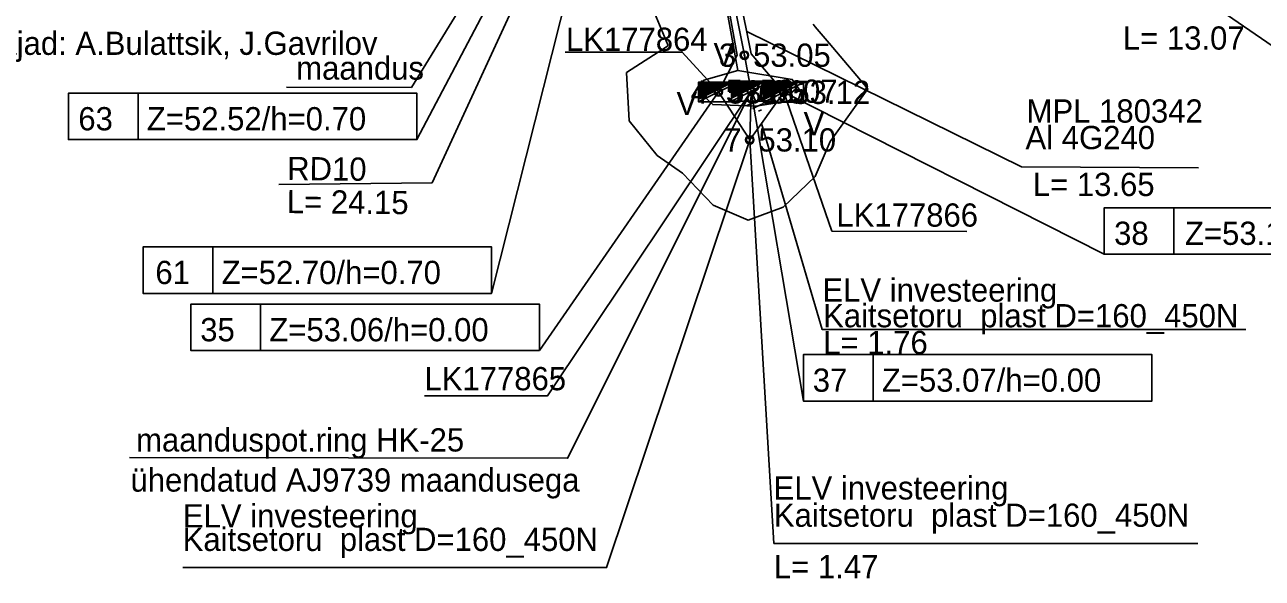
# Model space of a CAD drawing. Extents: x 592082 to 595437, y 6463338 to 6467739.
# Drawn here: x 592385.16 to 592422.46, y 6466209.4 to 6466226.07 of the extents above; entities that cross this region are included whole.
import ezdxf

# ---------------------------------------------------------------- set-up
doc = ezdxf.new("R2010")
doc.units = 0
for name, color, linetype in [('ABIJOONIS', 7, 'Continuous'), ('ELRAJATISMP', 7, 'Continuous'), ('KOORDPUNKT', 7, 'Continuous'), ('MOOTKORG-EH2000', 7, 'Continuous'), ('MOOTMPUNKT', 7, 'Continuous'), ('MOOTNR', 7, 'Continuous'), ('MOOTPIIR', 7, 'Continuous'), ('MPKAABEL', 7, 'Continuous'), ('RAJATIS', 7, 'Continuous'), ('TEE', 7, 'Continuous')]:
    doc.layers.add(name, color=color, linetype=linetype)

msp = doc.modelspace()

# ---------------------------------------------------------------- linework, layer by layer
at = {"layer": 'ABIJOONIS'}
for points in [[(592402.61, 6466231.398), (592399.232, 6466217.982), (592388.732, 6466217.982), (592388.732, 6466219.382), (592399.232, 6466219.382), (592399.232, 6466217.982)], [(592400.927, 6466230.114), (592396.98, 6466222.613), (592386.48, 6466222.613), (592386.48, 6466224.013), (592396.98, 6466224.013), (592396.98, 6466222.613)], [(592388.58, 6466222.613), (592388.58, 6466224.013)], [(592406.069, 6466224.05), (592400.672, 6466216.257), (592390.172, 6466216.257), (592390.172, 6466217.657), (592400.672, 6466217.657), (592400.672, 6466216.257)], [(592407.056, 6466224.073), (592408.631, 6466214.737), (592419.131, 6466214.737), (592419.131, 6466216.137), (592408.631, 6466216.137), (592408.631, 6466214.737)], [(592408.036, 6466224.039), (592417.694, 6466219.162), (592428.194, 6466219.162), (592428.194, 6466220.562), (592417.694, 6466220.562), (592417.694, 6466219.162)], [(592419.794, 6466219.162), (592419.794, 6466220.562)], [(592390.832, 6466217.982), (592390.832, 6466219.382)], [(592392.272, 6466216.257), (592392.272, 6466217.657)], [(592410.731, 6466214.737), (592410.731, 6466216.137)]]:
    msp.add_lwpolyline(points, dxfattribs=at)
at = {"layer": 'ELRAJATISMP'}
for p, q in [((592405.472, 6466224.344), (592405.476, 6466224.348)), ((592405.472, 6466224.33), (592405.49, 6466224.348)), ((592405.472, 6466224.316), (592405.504, 6466224.348)), ((592405.472, 6466224.302), (592405.518, 6466224.348)), ((592405.472, 6466224.288), (592405.532, 6466224.348)), ((592405.472, 6466224.274), (592405.547, 6466224.348)), ((592405.472, 6466224.259), (592405.561, 6466224.348)), ((592405.472, 6466224.245), (592405.575, 6466224.348)), ((592405.472, 6466224.231), (592405.589, 6466224.348)), ((592405.472, 6466224.217), (592405.603, 6466224.348)), ((592405.472, 6466224.203), (592405.617, 6466224.348)), ((592405.472, 6466224.189), (592405.631, 6466224.348)), ((592405.472, 6466224.175), (592405.646, 6466224.348)), ((592405.472, 6466224.16), (592405.66, 6466224.348)), ((592405.472, 6466224.146), (592405.674, 6466224.348)), ((592405.472, 6466224.132), (592405.688, 6466224.348)), ((592405.472, 6466224.118), (592405.702, 6466224.348)), ((592405.472, 6466224.104), (592405.716, 6466224.348)), ((592405.472, 6466224.09), (592405.73, 6466224.348)), ((592405.472, 6466224.076), (592405.745, 6466224.348)), ((592405.472, 6466224.061), (592405.759, 6466224.348)), ((592405.472, 6466224.047), (592405.773, 6466224.348)), ((592405.472, 6466224.033), (592405.787, 6466224.348)), ((592405.472, 6466224.019), (592405.801, 6466224.348)), ((592405.472, 6466224.005), (592405.815, 6466224.348)), ((592405.472, 6466223.991), (592405.829, 6466224.348)), ((592405.472, 6466223.977), (592405.844, 6466224.348)), ((592405.472, 6466223.962), (592405.858, 6466224.348)), ((592405.472, 6466223.948), (592405.872, 6466224.348)), ((592405.472, 6466223.934), (592405.886, 6466224.348)), ((592405.472, 6466223.92), (592405.9, 6466224.348)), ((592405.472, 6466223.906), (592405.914, 6466224.348)), ((592405.472, 6466223.892), (592405.928, 6466224.348)), ((592405.472, 6466223.878), (592405.943, 6466224.348)), ((592405.472, 6466223.863), (592405.957, 6466224.348)), ((592405.472, 6466223.849), (592405.971, 6466224.348)), ((592405.472, 6466223.836), (592405.985, 6466224.348)), ((592405.5, 6466223.85), (592405.999, 6466224.348)), ((592405.529, 6466223.864), (592406.013, 6466224.348)), ((592405.557, 6466223.878), (592406.027, 6466224.348)), ((592405.585, 6466223.892), (592406.042, 6466224.348)), ((592405.614, 6466223.906), (592406.056, 6466224.348)), ((592405.642, 6466223.92), (592406.07, 6466224.348)), ((592405.67, 6466223.935), (592406.084, 6466224.348)), ((592405.698, 6466223.949), (592406.098, 6466224.348)), ((592405.727, 6466223.963), (592406.112, 6466224.348)), ((592405.755, 6466223.977), (592406.126, 6466224.348)), ((592405.783, 6466223.991), (592406.141, 6466224.348)), ((592405.811, 6466224.005), (592406.155, 6466224.348)), ((592405.84, 6466224.019), (592406.169, 6466224.348)), ((592405.868, 6466224.033), (592406.183, 6466224.348)), ((592405.896, 6466224.047), (592406.197, 6466224.348)), ((592405.924, 6466224.062), (592406.211, 6466224.348)), ((592405.953, 6466224.076), (592406.225, 6466224.348)), ((592405.981, 6466224.09), (592406.24, 6466224.348)), ((592406.009, 6466224.104), (592406.254, 6466224.348)), ((592406.038, 6466224.118), (592406.268, 6466224.348)), ((592406.066, 6466224.132), (592406.282, 6466224.348)), ((592406.094, 6466224.146), (592406.296, 6466224.348)), ((592406.122, 6466224.16), (592406.31, 6466224.348)), ((592406.151, 6466224.175), (592406.324, 6466224.348)), ((592406.179, 6466224.189), (592406.339, 6466224.348)), ((592406.207, 6466224.203), (592406.353, 6466224.348)), ((592406.235, 6466224.217), (592406.367, 6466224.348)), ((592406.264, 6466224.231), (592406.381, 6466224.348)), ((592406.292, 6466224.245), (592406.395, 6466224.348)), ((592406.32, 6466224.259), (592406.409, 6466224.348)), ((592406.348, 6466224.273), (592406.423, 6466224.348)), ((592406.377, 6466224.288), (592406.438, 6466224.348)), ((592406.405, 6466224.302), (592406.452, 6466224.348)), ((592406.433, 6466224.316), (592406.466, 6466224.348)), ((592406.459, 6466224.367), (592406.463, 6466224.371)), ((592406.459, 6466224.353), (592406.477, 6466224.371)), ((592406.459, 6466224.339), (592406.491, 6466224.371)), ((592406.459, 6466224.325), (592406.505, 6466224.371)), ((592406.459, 6466224.311), (592406.519, 6466224.371)), ((592406.459, 6466224.297), (592406.534, 6466224.371)), ((592406.459, 6466224.282), (592406.548, 6466224.371)), ((592406.459, 6466224.268), (592406.562, 6466224.371)), ((592406.459, 6466224.254), (592406.576, 6466224.371)), ((592406.459, 6466224.24), (592406.59, 6466224.371)), ((592406.459, 6466224.226), (592406.604, 6466224.371)), ((592406.459, 6466224.212), (592406.618, 6466224.371)), ((592406.459, 6466224.198), (592406.633, 6466224.371)), ((592406.459, 6466224.183), (592406.647, 6466224.371)), ((592406.459, 6466224.169), (592406.661, 6466224.371)), ((592406.459, 6466224.155), (592406.675, 6466224.371)), ((592406.459, 6466224.141), (592406.689, 6466224.371)), ((592406.459, 6466224.127), (592406.703, 6466224.371)), ((592406.459, 6466224.113), (592406.717, 6466224.371)), ((592406.459, 6466224.099), (592406.732, 6466224.371)), ((592406.459, 6466224.084), (592406.746, 6466224.371)), ((592406.459, 6466224.07), (592406.76, 6466224.371)), ((592406.459, 6466224.056), (592406.774, 6466224.371)), ((592406.459, 6466224.042), (592406.788, 6466224.371)), ((592406.459, 6466224.028), (592406.802, 6466224.371)), ((592406.459, 6466224.014), (592406.816, 6466224.371)), ((592406.459, 6466224), (592406.831, 6466224.371)), ((592406.459, 6466223.985), (592406.845, 6466224.371)), ((592406.459, 6466223.971), (592406.859, 6466224.371)), ((592406.459, 6466223.957), (592406.873, 6466224.371)), ((592406.459, 6466223.943), (592406.887, 6466224.371)), ((592406.459, 6466223.929), (592406.901, 6466224.371)), ((592406.459, 6466223.915), (592406.915, 6466224.371)), ((592406.459, 6466223.901), (592406.93, 6466224.371)), ((592406.459, 6466223.886), (592406.944, 6466224.371)), ((592406.459, 6466223.872), (592406.958, 6466224.371)), ((592406.459, 6466223.859), (592406.972, 6466224.371)), ((592406.462, 6466224.33), (592406.48, 6466224.348)), ((592406.487, 6466223.873), (592406.986, 6466224.371)), ((592406.49, 6466224.344), (592406.494, 6466224.348)), ((592406.498, 6466224.348), (592406.666, 6466224.348)), ((592406.516, 6466223.887), (592407, 6466224.371)), ((592406.544, 6466223.901), (592407.014, 6466224.371)), ((592406.572, 6466223.915), (592407.029, 6466224.371)), ((592406.601, 6466223.929), (592407.043, 6466224.371)), ((592406.629, 6466223.943), (592407.057, 6466224.371)), ((592406.657, 6466223.958), (592407.071, 6466224.371)), ((592406.685, 6466223.972), (592407.085, 6466224.371)), ((592406.714, 6466223.986), (592407.099, 6466224.371)), ((592406.742, 6466224), (592407.113, 6466224.371)), ((592406.77, 6466224.014), (592407.128, 6466224.371)), ((592406.798, 6466224.028), (592407.142, 6466224.371)), ((592406.827, 6466224.042), (592407.156, 6466224.371)), ((592406.855, 6466224.056), (592407.17, 6466224.371)), ((592406.883, 6466224.07), (592407.184, 6466224.371)), ((592406.911, 6466224.085), (592407.198, 6466224.371)), ((592406.94, 6466224.099), (592407.212, 6466224.371)), ((592406.968, 6466224.113), (592407.227, 6466224.371)), ((592406.996, 6466224.127), (592407.241, 6466224.371)), ((592407.025, 6466224.141), (592407.255, 6466224.371)), ((592407.053, 6466224.155), (592407.269, 6466224.371)), ((592407.081, 6466224.169), (592407.283, 6466224.371)), ((592407.109, 6466224.183), (592407.297, 6466224.371)), ((592407.138, 6466224.198), (592407.311, 6466224.371)), ((592407.166, 6466224.212), (592407.326, 6466224.371)), ((592407.194, 6466224.226), (592407.34, 6466224.371)), ((592407.222, 6466224.24), (592407.354, 6466224.371)), ((592407.251, 6466224.254), (592407.368, 6466224.371)), ((592407.279, 6466224.268), (592407.382, 6466224.371)), ((592407.307, 6466224.282), (592407.396, 6466224.371)), ((592407.335, 6466224.296), (592407.41, 6466224.371)), ((592407.364, 6466224.311), (592407.425, 6466224.371)), ((592407.392, 6466224.325), (592407.439, 6466224.371)), ((592407.42, 6466224.339), (592407.453, 6466224.371)), ((592407.439, 6466224.333), (592407.443, 6466224.337)), ((592407.439, 6466224.319), (592407.457, 6466224.337)), ((592407.439, 6466224.305), (592407.471, 6466224.337)), ((592407.439, 6466224.291), (592407.485, 6466224.337)), ((592407.439, 6466224.277), (592407.499, 6466224.337)), ((592407.439, 6466224.263), (592407.514, 6466224.337)), ((592407.439, 6466224.248), (592407.528, 6466224.337)), ((592407.439, 6466224.234), (592407.542, 6466224.337)), ((592407.439, 6466224.22), (592407.556, 6466224.337)), ((592407.439, 6466224.206), (592407.57, 6466224.337)), ((592407.439, 6466224.192), (592407.584, 6466224.337)), ((592407.439, 6466224.178), (592407.598, 6466224.337)), ((592407.439, 6466224.164), (592407.613, 6466224.337)), ((592407.439, 6466224.149), (592407.627, 6466224.337)), ((592407.439, 6466224.135), (592407.641, 6466224.337)), ((592407.439, 6466224.121), (592407.655, 6466224.337)), ((592407.439, 6466224.107), (592407.669, 6466224.337)), ((592407.439, 6466224.093), (592407.683, 6466224.337)), ((592407.439, 6466224.079), (592407.697, 6466224.337)), ((592407.439, 6466224.065), (592407.712, 6466224.337)), ((592407.439, 6466224.05), (592407.726, 6466224.337)), ((592407.439, 6466224.036), (592407.74, 6466224.337)), ((592407.439, 6466224.022), (592407.754, 6466224.337)), ((592407.439, 6466224.008), (592407.768, 6466224.337)), ((592407.439, 6466223.994), (592407.782, 6466224.337)), ((592407.439, 6466223.98), (592407.796, 6466224.337)), ((592407.439, 6466223.966), (592407.811, 6466224.337)), ((592407.439, 6466223.951), (592407.825, 6466224.337)), ((592407.439, 6466223.937), (592407.839, 6466224.337)), ((592407.439, 6466223.923), (592407.853, 6466224.337)), ((592407.439, 6466223.909), (592407.867, 6466224.337)), ((592407.439, 6466223.895), (592407.881, 6466224.337)), ((592407.439, 6466223.881), (592407.895, 6466224.337)), ((592407.439, 6466223.867), (592407.91, 6466224.337)), ((592407.439, 6466223.852), (592407.924, 6466224.337)), ((592407.439, 6466223.838), (592407.938, 6466224.337)), ((592407.439, 6466223.825), (592407.952, 6466224.337)), ((592407.449, 6466224.353), (592407.467, 6466224.371)), ((592407.467, 6466223.839), (592407.966, 6466224.337)), ((592407.477, 6466224.367), (592407.481, 6466224.371)), ((592407.485, 6466224.371), (592407.653, 6466224.371)), ((592407.496, 6466223.853), (592407.98, 6466224.337)), ((592407.524, 6466223.867), (592407.994, 6466224.337)), ((592407.552, 6466223.881), (592408.009, 6466224.337)), ((592407.581, 6466223.895), (592408.023, 6466224.337)), ((592407.609, 6466223.909), (592408.037, 6466224.337)), ((592407.637, 6466223.924), (592408.051, 6466224.337)), ((592407.665, 6466223.938), (592408.065, 6466224.337)), ((592407.694, 6466223.952), (592408.079, 6466224.337)), ((592407.722, 6466223.966), (592408.093, 6466224.337)), ((592407.75, 6466223.98), (592408.108, 6466224.337)), ((592407.778, 6466223.994), (592408.122, 6466224.337)), ((592407.807, 6466224.008), (592408.136, 6466224.337)), ((592407.835, 6466224.022), (592408.15, 6466224.337)), ((592407.863, 6466224.036), (592408.164, 6466224.337)), ((592407.891, 6466224.051), (592408.178, 6466224.337)), ((592407.92, 6466224.065), (592408.192, 6466224.337)), ((592407.948, 6466224.079), (592408.207, 6466224.337)), ((592407.976, 6466224.093), (592408.221, 6466224.337)), ((592408.005, 6466224.107), (592408.235, 6466224.337)), ((592408.033, 6466224.121), (592408.249, 6466224.337)), ((592408.061, 6466224.135), (592408.263, 6466224.337)), ((592408.089, 6466224.149), (592408.277, 6466224.337)), ((592408.118, 6466224.164), (592408.291, 6466224.337)), ((592408.146, 6466224.178), (592408.306, 6466224.337)), ((592408.174, 6466224.192), (592408.32, 6466224.337)), ((592408.202, 6466224.206), (592408.334, 6466224.337)), ((592408.231, 6466224.22), (592408.348, 6466224.337)), ((592408.259, 6466224.234), (592408.362, 6466224.337)), ((592408.287, 6466224.248), (592408.376, 6466224.337)), ((592408.315, 6466224.262), (592408.39, 6466224.337)), ((592408.344, 6466224.277), (592408.405, 6466224.337)), ((592408.372, 6466224.291), (592408.419, 6466224.337)), ((592408.4, 6466224.305), (592408.433, 6466224.337)), ((592408.429, 6466224.319), (592408.447, 6466224.337)), ((592408.457, 6466224.333), (592408.461, 6466224.337)), ((592408.465, 6466224.337), (592408.633, 6466224.337)), ((592405.472, 6466223.835), (592405.472, 6466223.752)), ((592406.459, 6466223.858), (592406.459, 6466223.775)), ((592407.439, 6466223.824), (592407.439, 6466223.741))]:
    msp.add_line(p, q, dxfattribs=at)
for points in [[(592406.069, 6466224.05), (592404.974, 6466225.253), (592401.445, 6466225.253)], [(592407.056, 6466224.073), (592400.918, 6466214.898), (592397.209, 6466214.898)], [(592408.036, 6466224.039), (592409.49, 6466219.86), (592413.556, 6466219.843)]]:
    msp.add_lwpolyline(points, dxfattribs=at)
for points in [[(592406.666, 6466224.348), (592405.472, 6466223.752), (592406.666, 6466223.752)], [(592405.472, 6466223.835), (592405.472, 6466224.348), (592406.498, 6466224.348)], [(592407.653, 6466224.371), (592406.459, 6466223.775), (592407.653, 6466223.775)], [(592406.459, 6466223.858), (592406.459, 6466224.371), (592407.485, 6466224.371)], [(592408.633, 6466224.337), (592407.439, 6466223.741), (592408.633, 6466223.741)], [(592407.439, 6466223.824), (592407.439, 6466224.337), (592408.465, 6466224.337)]]:
    msp.add_lwpolyline(points, close=True, dxfattribs=at)
at = {"layer": 'KOORDPUNKT'}
for centre, radius in [((592406.852, 6466225.157), 0.125), ((592406.852, 6466225.157), 0.0125), ((592406.852, 6466225.157), 0.011), ((592406.852, 6466225.157), 0.00955), ((592406.852, 6466225.157), 0.00807), ((592406.852, 6466225.157), 0.00659), ((592406.852, 6466225.157), 0.00511), ((592406.852, 6466225.157), 0.00363), ((592406.852, 6466225.157), 0.00215), ((592407.056, 6466224.073), 0.125), ((592406.069, 6466224.05), 0.125), ((592406.069, 6466224.05), 0.0125), ((592406.069, 6466224.05), 0.011), ((592406.069, 6466224.05), 0.00955), ((592406.069, 6466224.05), 0.00807), ((592406.069, 6466224.05), 0.00659), ((592406.069, 6466224.05), 0.00511), ((592406.069, 6466224.05), 0.00363), ((592406.069, 6466224.05), 0.00215), ((592407.056, 6466224.073), 0.0125), ((592407.056, 6466224.073), 0.011), ((592407.056, 6466224.073), 0.00955), ((592407.056, 6466224.073), 0.00807), ((592407.056, 6466224.073), 0.00659), ((592407.056, 6466224.073), 0.00511), ((592407.056, 6466224.073), 0.00363), ((592407.056, 6466224.073), 0.00215), ((592408.036, 6466224.039), 0.125), ((592408.036, 6466224.039), 0.0125), ((592408.036, 6466224.039), 0.011), ((592408.036, 6466224.039), 0.00955), ((592408.036, 6466224.039), 0.00807), ((592408.036, 6466224.039), 0.00659), ((592408.036, 6466224.039), 0.00511), ((592408.036, 6466224.039), 0.00363), ((592408.036, 6466224.039), 0.00215), ((592407.012, 6466222.605), 0.125), ((592407.012, 6466222.605), 0.0125), ((592407.012, 6466222.605), 0.011), ((592407.012, 6466222.605), 0.00955), ((592407.012, 6466222.605), 0.00807), ((592407.012, 6466222.605), 0.00659), ((592407.012, 6466222.605), 0.00511), ((592407.012, 6466222.605), 0.00363), ((592407.012, 6466222.605), 0.00215)]:
    msp.add_circle(centre, radius, dxfattribs=at)
at = {"layer": 'MOOTMPUNKT'}
for centre in [(592406.852, 6466225.157), (592406.069, 6466224.05), (592407.056, 6466224.073), (592408.036, 6466224.039), (592407.012, 6466222.605)]:
    msp.add_circle(centre, 0.1, dxfattribs=at)
at = {"layer": 'MOOTPIIR'}
msp.add_lwpolyline([(592403.388, 6466228.25), (592404.546, 6466225.467), (592404.53, 6466225.434), (592403.301, 6466224.632), (592403.379, 6466223.177), (592404.222, 6466222.14), (592404.981, 6466221.598), (592405.908, 6466220.637), (592406.961, 6466220.184), (592408.019, 6466220.574), (592408.98, 6466221.501), (592409.433, 6466222.554), (592409.518, 6466222.672), (592410.567, 6466224.141), (592409.403, 6466225.521), (592408.985, 6466226.016), (592408.918, 6466226.095)], dxfattribs=at)
at = {"layer": 'MPKAABEL'}
for p, q in [((592405.723, 6466229.876), (592406.648, 6466224.697)), ((592406.069, 6466224.05), (592407.012, 6466222.605)), ((592407.056, 6466224.073), (592407.012, 6466222.605)), ((592408.036, 6466224.039), (592407.012, 6466222.605))]:
    msp.add_line(p, q, dxfattribs=at)
for points in [[(592408.036, 6466224.039), (592407.058, 6466225.198), (592406.326, 6466228.858), (592406.09, 6466232.311), (592405.513, 6466234.668), (592403.331, 6466234.927), (592402.997, 6466234.373)], [(592407.056, 6466224.073), (592406.852, 6466225.157), (592406.117, 6466228.831), (592405.926, 6466232.295), (592405.424, 6466234.557), (592403.382, 6466234.799), (592403.129, 6466234.375)], [(592406.069, 6466224.05), (592406.634, 6466225.157), (592405.982, 6466228.801), (592405.708, 6466232.295), (592405.292, 6466234.404), (592403.453, 6466234.687), (592403.129, 6466234.375)], [(592401.322, 6466229.725), (592397.438, 6466221.313), (592392.817, 6466221.263)], [(592400.196, 6466229.686), (592396.817, 6466224.18), (592393.053, 6466224.197)], [(592406.922, 6466225.876), (592415.198, 6466221.789), (592420.534, 6466221.763)], [(592407.056, 6466224.073), (592401.524, 6466213.014), (592388.317, 6466213.031)], [(592407.485, 6466223.895), (592406.906, 6466223.633)], [(592407.056, 6466224.073), (592407.196, 6466223.764)], [(592407.425, 6466223.703), (592407.09, 6466223.552)], [(592407.365, 6466223.511), (592407.274, 6466223.47)], [(592407.368, 6466223.104), (592409.19, 6466216.896), (592421.964, 6466216.896)], [(592407.012, 6466222.605), (592402.697, 6466209.72), (592389.923, 6466209.72)], [(592407.012, 6466222.605), (592407.74, 6466210.448), (592420.514, 6466210.448)]]:
    msp.add_lwpolyline(points, dxfattribs=at)
msp.add_lwpolyline([(592406.648, 6466224.697), (592408.293, 6466224.427), (592408.556, 6466224.068), (592408.484, 6466223.82), (592407.192, 6466223.619), (592405.896, 6466223.668), (592405.537, 6466224.012), (592405.625, 6466224.403)], close=True, dxfattribs=at)
at = {"layer": 'TEE'}
msp.add_lwpolyline([(592408.764, 6466249.828), (592407.446, 6466245.456), (592406.752, 6466242.846), (592406.442, 6466240.502), (592406.831, 6466238.914), (592407.484, 6466237.872), (592408.832, 6466236.834), (592411.597, 6466233.841), (592415.522, 6466230.408), (592427.423, 6466222.233), (592430.48, 6466220.001)], dxfattribs=at)

# ---------------------------------------------------------------- texts
at = {"layer": 'ABIJOONIS'}
for s, p in [('63', (592386.778, 6466222.893)), ('Z=52.52/h=0.70', (592388.843, 6466222.893)), ('38', (592417.991, 6466219.442)), ('Z=53.12/h=0.00', (592420.126, 6466219.442)), ('61', (592389.1, 6466218.262)), ('Z=52.70/h=0.70', (592391.095, 6466218.262)), ('35', (592390.452, 6466216.537)), ('Z=53.06/h=0.00', (592392.534, 6466216.537)), ('37', (592408.911, 6466215.017)), ('Z=53.07/h=0.00', (592410.993, 6466215.017))]:
    msp.add_text(s, height=0.7, dxfattribs=at).set_placement(p)
at = {"layer": 'ELRAJATISMP'}
for s, p in [('LK177864', (592401.473, 6466225.286)), ('V', (592405.919, 6466224.827)), ('V', (592404.804, 6466223.353)), ('V', (592408.635, 6466222.743)), ('LK177866', (592409.622, 6466219.992)), ('LK177865', (592397.209, 6466215.062))]:
    msp.add_text(s, height=0.7, dxfattribs=at).set_placement(p)
at = {"layer": 'MOOTKORG-EH2000'}
for s, p in [(' 53.05', (592406.852, 6466224.807)), (' 53.06', (592406.069, 6466223.7)), (' 53.07', (592407.056, 6466223.723)), (' 53.12', (592408.036, 6466223.689)), (' 53.10', (592407.012, 6466222.255))]:
    msp.add_text(s, height=0.7, dxfattribs=at).set_placement(p)
at = {"layer": 'MOOTNR'}
for s, p in [('3 ', (592406.082, 6466224.807)), ('4 ', (592405.229, 6466223.7)), ('5 ', (592406.286, 6466223.723)), ('6 ', (592407.266, 6466223.689)), ('7 ', (592406.242, 6466222.255))]:
    msp.add_text(s, height=0.7, dxfattribs=at).set_placement(p)
at = {"layer": 'MPKAABEL'}
for s, p in [('L= 13.07', (592418.256, 6466225.325)), ('MPL 180342', (592415.355, 6466223.126)), ('Al 4G240', (592415.322, 6466222.326)), ('L= 13.65', (592415.542, 6466220.914)), ('ELV investeering', (592409.201, 6466217.732)), ('Kaitsetoru  plast D=160_450N', (592409.222, 6466216.959)), ('L= 1.76', (592409.227, 6466216.151)), ('maanduspot.ring HK-25', (592388.519, 6466213.216)), ('ühendatud AJ9739 maandusega', (592388.349, 6466212.008)), ('ELV investeering', (592407.73, 6466211.77)), ('ELV investeering', (592389.929, 6466210.928)), ('Kaitsetoru  plast D=160_450N', (592407.74, 6466210.948)), ('Kaitsetoru  plast D=160_450N', (592389.923, 6466210.22)), ('L= 1.47', (592407.74, 6466209.398))]:
    msp.add_text(s, height=0.7, dxfattribs=at).set_placement(p)
for s, rotation, p in [('maandus', 359.9773, (592393.344, 6466224.421)), ('RD10', 359.4518, (592393.068, 6466221.395)), ('L= 24.15', 359.4518, (592393.059, 6466220.4))]:
    msp.add_text(s, height=0.7, rotation=rotation, dxfattribs=at).set_placement(p)
at = {"layer": 'RAJATIS'}
msp.add_text('20.05.2021 teostajad: A.Bulattsik, J.Gavrilov', height=0.7, dxfattribs=at).set_placement((592377.426, 6466225.167))

doc.saveas('drawing.dxf')
